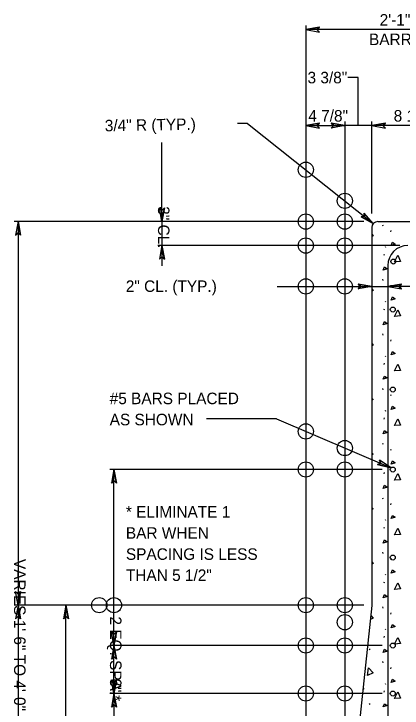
# Model space of a CAD drawing. Extents: x -26.5 to -19.2, y -3.6 to 6.6.
# Drawn here: x -25.3 to -23.277, y 2.961 to 6.577 of the extents above; entities that cross this region are included whole.
import ezdxf

# ---------------------------------------------------------------- set-up
doc = ezdxf.new("R2010")
doc.units = 0
for name, color, linetype in [('ANNO-WOUT', 7, 'Continuous'), ('DETL-DIMS', 7, 'Continuous'), ('DETL-PATT', 7, 'Continuous'), ('Level 10', 7, 'Continuous'), ('Level 12', 7, 'Continuous'), ('SUPR-PARA_P', 7, 'Continuous'), ('SUPR-RFRC', 7, 'Continuous')]:
    doc.layers.add(name, color=color, linetype=linetype)

msp = doc.modelspace()

# ---------------------------------------------------------------- linework, layer by layer
at = {"layer": 'ANNO-WOUT'}
for centre in [(-23.7787, 5.7653), (-23.5755, 5.6033), (-23.7787, 5.4955), (-23.5755, 5.4955), (-23.7787, 5.3705), (-23.5755, 5.3705), (-23.7787, 5.1576), (-23.5755, 5.1576), (-23.7787, 4.4024), (-23.5755, 4.3158), (-23.7787, 4.2039), (-23.5755, 4.2039), (-24.8555, 3.4973), (-24.7787, 3.4973), (-23.7787, 3.4973), (-23.5755, 3.4973), (-23.5755, 3.4086), (-23.7787, 3.2872), (-23.5755, 3.2872), (-23.7787, 3.0372), (-23.5755, 3.0372)]:
    msp.add_circle(centre, 0.0397, dxfattribs=at)
at = {"layer": 'DETL-DIMS'}
for p, q in [((-23.7787, 6.4955), (-23.7072, 6.508)), ((-23.7787, 6.4955), (-23.7071, 6.4828)), ((-23.7072, 6.508), (-23.7207, 6.4955)), ((-23.7207, 6.4955), (-23.7071, 6.4828)), ((-23.7787, 5.9955), (-23.7072, 6.008)), ((-23.7072, 6.008), (-23.7207, 5.9955)), ((-23.5755, 5.9955), (-23.647, 6.008)), ((-23.647, 6.008), (-23.6335, 5.9955)), ((-23.4349, 5.9955), (-23.3634, 6.008)), ((-23.3634, 6.008), (-23.3769, 5.9955)), ((-23.7787, 5.9955), (-23.7071, 5.9828)), ((-23.7207, 5.9955), (-23.7071, 5.9828)), ((-23.5755, 5.9955), (-23.647, 5.9828)), ((-23.6335, 5.9955), (-23.647, 5.9828)), ((-23.4349, 5.9955), (-23.3634, 5.9828)), ((-23.3769, 5.9955), (-23.3634, 5.9828)), ((-24.5286, 5.4955), (-24.5413, 5.567)), ((-24.5286, 5.5535), (-24.5413, 5.567)), ((-24.5286, 5.4955), (-24.5161, 5.567)), ((-24.5161, 5.567), (-24.5286, 5.5535)), ((-23.4271, 5.4849), (-23.4751, 5.5395)), ((-23.4725, 5.5211), (-23.4751, 5.5395)), ((-23.4908, 5.5197), (-23.4725, 5.5211)), ((-23.4271, 5.4849), (-23.4908, 5.5197)), ((-25.2783, 5.4955), (-25.291, 5.424)), ((-25.2783, 5.4955), (-25.2658, 5.424)), ((-25.2783, 5.4375), (-25.291, 5.424)), ((-25.2658, 5.424), (-25.2783, 5.4375)), ((-24.5286, 5.3705), (-24.5413, 5.299)), ((-24.5286, 5.3705), (-24.5161, 5.299)), ((-24.5286, 5.3125), (-24.5413, 5.299)), ((-24.5161, 5.299), (-24.5286, 5.3125)), ((-23.4349, 5.1576), (-23.5064, 5.1701)), ((-23.5064, 5.1701), (-23.4929, 5.1576)), ((-23.4349, 5.1576), (-23.5064, 5.1449)), ((-23.4929, 5.1576), (-23.5064, 5.1449)), ((-23.3516, 5.1576), (-23.2801, 5.1701)), ((-23.3516, 5.1576), (-23.2801, 5.1449)), ((-23.2801, 5.1701), (-23.2936, 5.1576)), ((-23.2936, 5.1576), (-23.2801, 5.1449)), ((-23.4054, 4.2296), (-23.3881, 4.2358)), ((-23.3347, 4.2131), (-23.3955, 4.2528)), ((-23.3881, 4.2358), (-23.3955, 4.2528)), ((-24.7787, 4.2039), (-24.7913, 4.1324)), ((-24.7787, 4.2039), (-24.7661, 4.1324)), ((-23.3347, 4.2131), (-23.4054, 4.2296)), ((-24.7787, 4.1459), (-24.7913, 4.1324)), ((-24.7661, 4.1324), (-24.7787, 4.1459)), ((-25.2787, 3.4973), (-25.2913, 3.5689)), ((-25.2787, 3.5553), (-25.2913, 3.5689)), ((-25.2787, 3.4973), (-25.2661, 3.5688)), ((-25.2661, 3.5688), (-25.2787, 3.5553)), ((-25.2787, 3.4973), (-25.2913, 3.4258)), ((-25.2787, 3.4973), (-25.2661, 3.4259)), ((-25.0287, 3.4973), (-25.0413, 3.4258)), ((-25.0287, 3.4973), (-25.0161, 3.4259)), ((-25.2787, 3.4393), (-25.2913, 3.4258)), ((-25.2661, 3.4259), (-25.2787, 3.4393)), ((-25.0287, 3.4393), (-25.0413, 3.4258)), ((-25.0161, 3.4259), (-25.0287, 3.4393)), ((-24.7787, 3.2872), (-24.7913, 3.3587)), ((-24.7787, 3.3452), (-24.7913, 3.3587)), ((-24.7787, 3.2872), (-24.7661, 3.3587)), ((-24.7661, 3.3587), (-24.7787, 3.3452)), ((-24.7787, 3.2872), (-24.7913, 3.2157)), ((-24.7787, 3.2872), (-24.7661, 3.2157)), ((-24.7787, 3.2292), (-24.7913, 3.2157)), ((-24.7661, 3.2157), (-24.7787, 3.2292)), ((-24.7787, 3.0372), (-24.7913, 3.1087)), ((-24.7787, 3.0952), (-24.7913, 3.1087)), ((-24.7787, 3.0372), (-24.7661, 3.1087)), ((-24.7661, 3.1087), (-24.7787, 3.0952)), ((-24.7787, 3.0372), (-24.7913, 2.9657)), ((-24.7787, 3.0372), (-24.7661, 2.9657)), ((-24.7787, 2.9792), (-24.7913, 2.9657)), ((-24.7661, 2.9657), (-24.7787, 2.9792))]:
    msp.add_line(p, q, dxfattribs=at)
for points in [[(-23.7072, 6.508), (-23.7787, 6.4955), (-23.7071, 6.4828), (-23.7207, 6.4955)], [(-23.7072, 6.008), (-23.7787, 5.9955), (-23.7071, 5.9828), (-23.7207, 5.9955)], [(-23.647, 6.008), (-23.5755, 5.9955), (-23.647, 5.9828), (-23.6335, 5.9955)], [(-23.3634, 6.008), (-23.4349, 5.9955), (-23.3634, 5.9828), (-23.3769, 5.9955)], [(-24.5161, 5.567), (-24.5286, 5.4955), (-24.5413, 5.567), (-24.5286, 5.5535)], [(-23.4908, 5.5197), (-23.4271, 5.4849), (-23.4751, 5.5395), (-23.4725, 5.5211)], [(-25.2658, 5.424), (-25.2783, 5.4955), (-25.291, 5.424), (-25.2783, 5.4375)], [(-24.5161, 5.299), (-24.5286, 5.3705), (-24.5413, 5.299), (-24.5286, 5.3125)], [(-23.5064, 5.1701), (-23.4349, 5.1576), (-23.5064, 5.1449), (-23.4929, 5.1576)], [(-23.2801, 5.1701), (-23.3516, 5.1576), (-23.2801, 5.1449), (-23.2936, 5.1576)], [(-23.4054, 4.2296), (-23.3347, 4.2131), (-23.3955, 4.2528), (-23.3881, 4.2358)], [(-24.7661, 4.1324), (-24.7787, 4.2039), (-24.7913, 4.1324), (-24.7787, 4.1459)], [(-25.2661, 3.5688), (-25.2787, 3.4973), (-25.2913, 3.5689), (-25.2787, 3.5553)], [(-25.2661, 3.4259), (-25.2787, 3.4973), (-25.2913, 3.4258), (-25.2787, 3.4393)], [(-25.0161, 3.4259), (-25.0287, 3.4973), (-25.0413, 3.4258), (-25.0287, 3.4393)], [(-24.7661, 3.3587), (-24.7787, 3.2872), (-24.7913, 3.3587), (-24.7787, 3.3452)], [(-24.7661, 3.2157), (-24.7787, 3.2872), (-24.7913, 3.2157), (-24.7787, 3.2292)], [(-24.7661, 3.1087), (-24.7787, 3.0372), (-24.7913, 3.1087), (-24.7787, 3.0952)], [(-24.7661, 2.9657), (-24.7787, 3.0372), (-24.7913, 2.9657), (-24.7787, 2.9792)]]:
    msp.add_lwpolyline(points, close=True, dxfattribs=at)
at = {"layer": 'DETL-PATT'}
for p, q in [((-23.3789, 5.4792), (-23.3781, 5.473)), ((-23.3356, 5.4421), (-23.3333, 5.4483)), ((-23.3657, 5.3656), (-23.3634, 5.3617)), ((-23.3711, 5.32), (-23.3688, 5.3262)), ((-23.3789, 5.1948), (-23.3781, 5.1886)), ((-23.3356, 5.1577), (-23.3333, 5.1639)), ((-23.3657, 5.0812), (-23.3634, 5.0773)), ((-23.3711, 5.0356), (-23.3688, 5.0417)), ((-23.3789, 4.9103), (-23.3781, 4.9042)), ((-23.3356, 4.8732), (-23.3333, 4.8794)), ((-23.3657, 4.7967), (-23.3634, 4.7929)), ((-23.3711, 4.7511), (-23.3688, 4.7573)), ((-23.3789, 4.6259), (-23.3781, 4.6197)), ((-23.3356, 4.5888), (-23.3333, 4.595)), ((-23.3657, 4.5123), (-23.3634, 4.5084)), ((-23.3711, 4.4667), (-23.3688, 4.4729)), ((-23.3789, 4.3415), (-23.3781, 4.3353)), ((-23.3356, 4.3044), (-23.3333, 4.3105)), ((-23.3657, 4.2278), (-23.3634, 4.224)), ((-23.3711, 4.1822), (-23.3688, 4.1884)), ((-23.3789, 4.057), (-23.3781, 4.0508)), ((-23.3356, 4.0199), (-23.3333, 4.0261)), ((-23.3657, 3.9434), (-23.3634, 3.9395)), ((-23.3711, 3.8978), (-23.3688, 3.904)), ((-23.3789, 3.7726), (-23.3781, 3.7664)), ((-23.3356, 3.7355), (-23.3333, 3.7417)), ((-23.3657, 3.659), (-23.3634, 3.6551)), ((-23.3711, 3.6134), (-23.3688, 3.6195)), ((-23.3789, 3.4881), (-23.3781, 3.482)), ((-23.3356, 3.451), (-23.3333, 3.4572)), ((-23.3657, 3.3745), (-23.3634, 3.3706)), ((-23.3711, 3.3289), (-23.3688, 3.3351)), ((-23.4484, 3.2694), (-23.4453, 3.2648)), ((-23.3789, 3.2037), (-23.3781, 3.1975)), ((-23.3356, 3.1666), (-23.3333, 3.1728)), ((-23.3657, 3.0901), (-23.3634, 3.0862)), ((-23.4786, 3.0592), (-23.4755, 3.0653)), ((-23.3711, 3.0445), (-23.3688, 3.0507)), ((-23.4484, 2.985), (-23.4453, 2.9803))]:
    msp.add_line(p, q, dxfattribs=at)
for points in [[(-23.4349, 5.4291), (-23.4276, 5.4213), (-23.4349, 5.4178)], [(-23.3348, 5.3702), (-23.3263, 5.3873), (-23.3124, 5.3772), (-23.3348, 5.3702)], [(-23.317, 5.286), (-23.2985, 5.3208), (-23.2846, 5.2883), (-23.317, 5.286)], [(-23.3758, 5.2427), (-23.368, 5.2597), (-23.3541, 5.2497), (-23.3758, 5.2427)], [(-23.4349, 5.1446), (-23.4276, 5.1368), (-23.4349, 5.1333)], [(-23.3348, 5.0858), (-23.3263, 5.1028), (-23.3124, 5.0928), (-23.3348, 5.0858)], [(-23.317, 5.0016), (-23.2985, 5.0363), (-23.2846, 5.0039), (-23.317, 5.0016)], [(-23.3758, 4.9583), (-23.368, 4.9753), (-23.3541, 4.9652), (-23.3758, 4.9583)], [(-23.4349, 4.8602), (-23.4276, 4.8524), (-23.4349, 4.8489)], [(-23.3348, 4.8014), (-23.3263, 4.8184), (-23.3124, 4.8083), (-23.3348, 4.8014)], [(-23.317, 4.7171), (-23.2985, 4.7519), (-23.2846, 4.7194), (-23.317, 4.7171)], [(-23.3758, 4.6738), (-23.368, 4.6908), (-23.3541, 4.6808), (-23.3758, 4.6738)], [(-23.4349, 4.5757), (-23.4276, 4.5679), (-23.4349, 4.5645)], [(-23.3348, 4.5169), (-23.3263, 4.5339), (-23.3124, 4.5239), (-23.3348, 4.5169)], [(-23.317, 4.4327), (-23.2985, 4.4675), (-23.2846, 4.435), (-23.317, 4.4327)], [(-23.3758, 4.3894), (-23.368, 4.4064), (-23.3541, 4.3963), (-23.3758, 4.3894)], [(-23.4349, 4.2913), (-23.4276, 4.2835), (-23.4349, 4.28)], [(-23.3348, 4.2325), (-23.3263, 4.2495), (-23.3124, 4.2394), (-23.3348, 4.2325)], [(-23.317, 4.1482), (-23.2985, 4.183), (-23.2846, 4.1505), (-23.317, 4.1482)], [(-23.3758, 4.1049), (-23.368, 4.1219), (-23.3541, 4.1119), (-23.3758, 4.1049)], [(-23.4349, 4.0069), (-23.4276, 3.999), (-23.4349, 3.9956)], [(-23.3348, 3.948), (-23.3263, 3.965), (-23.3124, 3.955), (-23.3348, 3.948)], [(-23.317, 3.8638), (-23.2985, 3.8986), (-23.2846, 3.8661), (-23.317, 3.8638)], [(-23.3758, 3.8205), (-23.368, 3.8375), (-23.3541, 3.8275), (-23.3758, 3.8205)], [(-23.4349, 3.7224), (-23.4276, 3.7146), (-23.4349, 3.7111)], [(-23.3348, 3.6636), (-23.3263, 3.6806), (-23.3124, 3.6705), (-23.3348, 3.6636)], [(-23.317, 3.5793), (-23.2985, 3.6141), (-23.2846, 3.5817), (-23.317, 3.5793)], [(-23.3758, 3.5361), (-23.368, 3.5531), (-23.3541, 3.543), (-23.3758, 3.5361)], [(-23.4404, 3.4438), (-23.4276, 3.4302), (-23.4425, 3.4231)], [(-23.3348, 3.3792), (-23.3263, 3.3962), (-23.3124, 3.3861), (-23.3348, 3.3792)], [(-23.317, 3.2949), (-23.2985, 3.3297), (-23.2846, 3.2972), (-23.317, 3.2949)], [(-23.3758, 3.2516), (-23.368, 3.2686), (-23.3541, 3.2586), (-23.3758, 3.2516)], [(-23.4569, 3.1318), (-23.4515, 3.1712), (-23.4276, 3.1457), (-23.4569, 3.1318)], [(-23.3348, 3.0947), (-23.3263, 3.1117), (-23.3124, 3.1017), (-23.3348, 3.0947)], [(-23.317, 3.0105), (-23.2985, 3.0452), (-23.2846, 3.0128), (-23.317, 3.0105)], [(-23.3758, 2.9672), (-23.368, 2.9842), (-23.3541, 2.9741), (-23.3758, 2.9672)]]:
    msp.add_lwpolyline(points, dxfattribs=at)
at = {"layer": 'Level 10'}
for p, q in [((-23.7787, 6.5163), (-23.7787, 1.9121)), ((-22.737, 6.4955), (-23.7787, 6.4955)), ((-23.5052, 6.2455), (-23.559, 6.2455)), ((-23.5052, 5.9955), (-23.5052, 6.2455)), ((-24.0819, 6.0071), (-24.1357, 6.0071)), ((-24.0819, 6.0071), (-23.4271, 5.4849)), ((-23.5755, 6.0163), (-23.5755, 2.2464)), ((-23.4349, 5.5371), (-23.4349, 6.0163)), ((-23.7787, 5.9955), (-23.5755, 5.9955)), ((-23.4348, 5.9955), (-23.5755, 5.9955)), ((-23.0807, 5.9955), (-23.4349, 5.9955)), ((-24.5286, 5.4955), (-24.5286, 5.9067)), ((-23.4765, 5.4955), (-25.2995, 5.4955)), ((-25.2787, 5.4955), (-25.2787, 3.4973)), ((-24.5286, 5.4955), (-24.5286, 5.3705)), ((-23.289, 5.3705), (-24.5494, 5.3705)), ((-24.5286, 5.3705), (-24.5286, 5.265)), ((-23.9279, 5.1576), (-23.4349, 5.1576)), ((-23.4349, 5.1576), (-23.3516, 5.1576)), ((-23.2352, 5.1576), (-23.3516, 5.1576)), ((-23.9322, 4.468), (-24.2967, 4.468)), ((-23.9322, 4.468), (-23.3347, 4.2131)), ((-23.3802, 4.2039), (-24.7995, 4.2039)), ((-24.7787, 3.2872), (-24.7787, 4.2039)), ((-23.4765, 3.4973), (-25.2995, 3.4973)), ((-25.2787, 3.4973), (-25.2787, 1.7455)), ((-25.0287, 2.1654), (-25.0287, 3.4973)), ((-23.3802, 3.2872), (-24.7995, 3.2872)), ((-24.7787, 3.0372), (-24.7787, 3.2872)), ((-23.3802, 3.0372), (-24.7995, 3.0372)), ((-24.7787, 3.0372), (-24.7787, 2.6205))]:
    msp.add_line(p, q, dxfattribs=at)
at = {"layer": 'SUPR-PARA_P'}
for p, q in [((-23.4349, 5.4643), (-23.4349, 3.4955)), ((-23.4036, 5.4955), (-23.1089, 5.4955)), ((-23.4349, 3.4955), (-23.5616, 2.2941))]:
    msp.add_line(p, q, dxfattribs=at)
msp.add_arc((-23.4036, 5.4643), 0.0312, 90, 180, dxfattribs=at)
at = {"layer": 'SUPR-RFRC'}
msp.add_line((-23.3516, 5.2664), (-23.3516, 2.8757), dxfattribs=at)
for centre in [(-23.3227, 5.2872), (-23.3255, 5.0372), (-23.3255, 4.6205), (-23.3255, 4.2039), (-23.3255, 3.7455), (-23.3255, 3.2872), (-23.3255, 3.0372)]:
    msp.add_circle(centre, 0.013, dxfattribs=at)
msp.add_arc((-23.2474, 5.2664), 0.1042, 90, 180, dxfattribs=at)

# ---------------------------------------------------------------- texts
at = {"layer": 'Level 12'}
for s, p in [('2\'-1"', (-23.394, 6.5163)), ('BARRIER', (-23.4494, 6.4147)), ('3 3/8"', (-23.7699, 6.2155)), ('4 7/8"', (-23.7658, 6.0163)), ('8 1/2"', (-23.3209, 6.0163)), ('2" CL. (TYP.)', (-24.717, 5.1289)), ('#5 BARS PLACED ', (-24.8009, 4.5443)), ('AS SHOWN', (-24.8009, 4.4342)), ('* ELIMINATE 1 ', (-24.7165, 3.9534)), ('BAR WHEN ', (-24.7165, 3.8434)), ('SPACING IS LESS ', (-24.7165, 3.7334)), ('THAN 5 1/2"', (-24.7165, 3.6234))]:
    msp.add_text(s, height=0.06001, dxfattribs=at).set_placement(p)
for s, rotation, p in [('3/4" R (TYP.)', 1, (-24.8259, 5.9652)), ('3" CL.', 270, (-24.5494, 5.5753)), ('VARIES 1\'-6" TO 4\'-0" MAX.', 270, (-25.2995, 3.7381)), ('2 EQ. SPA.*', 270, (-24.7995, 3.4388)), ('6"', 270, (-24.7995, 3.116))]:
    msp.add_text(s, height=0.06001, rotation=rotation, dxfattribs=at).set_placement(p)

doc.saveas('drawing.dxf')
